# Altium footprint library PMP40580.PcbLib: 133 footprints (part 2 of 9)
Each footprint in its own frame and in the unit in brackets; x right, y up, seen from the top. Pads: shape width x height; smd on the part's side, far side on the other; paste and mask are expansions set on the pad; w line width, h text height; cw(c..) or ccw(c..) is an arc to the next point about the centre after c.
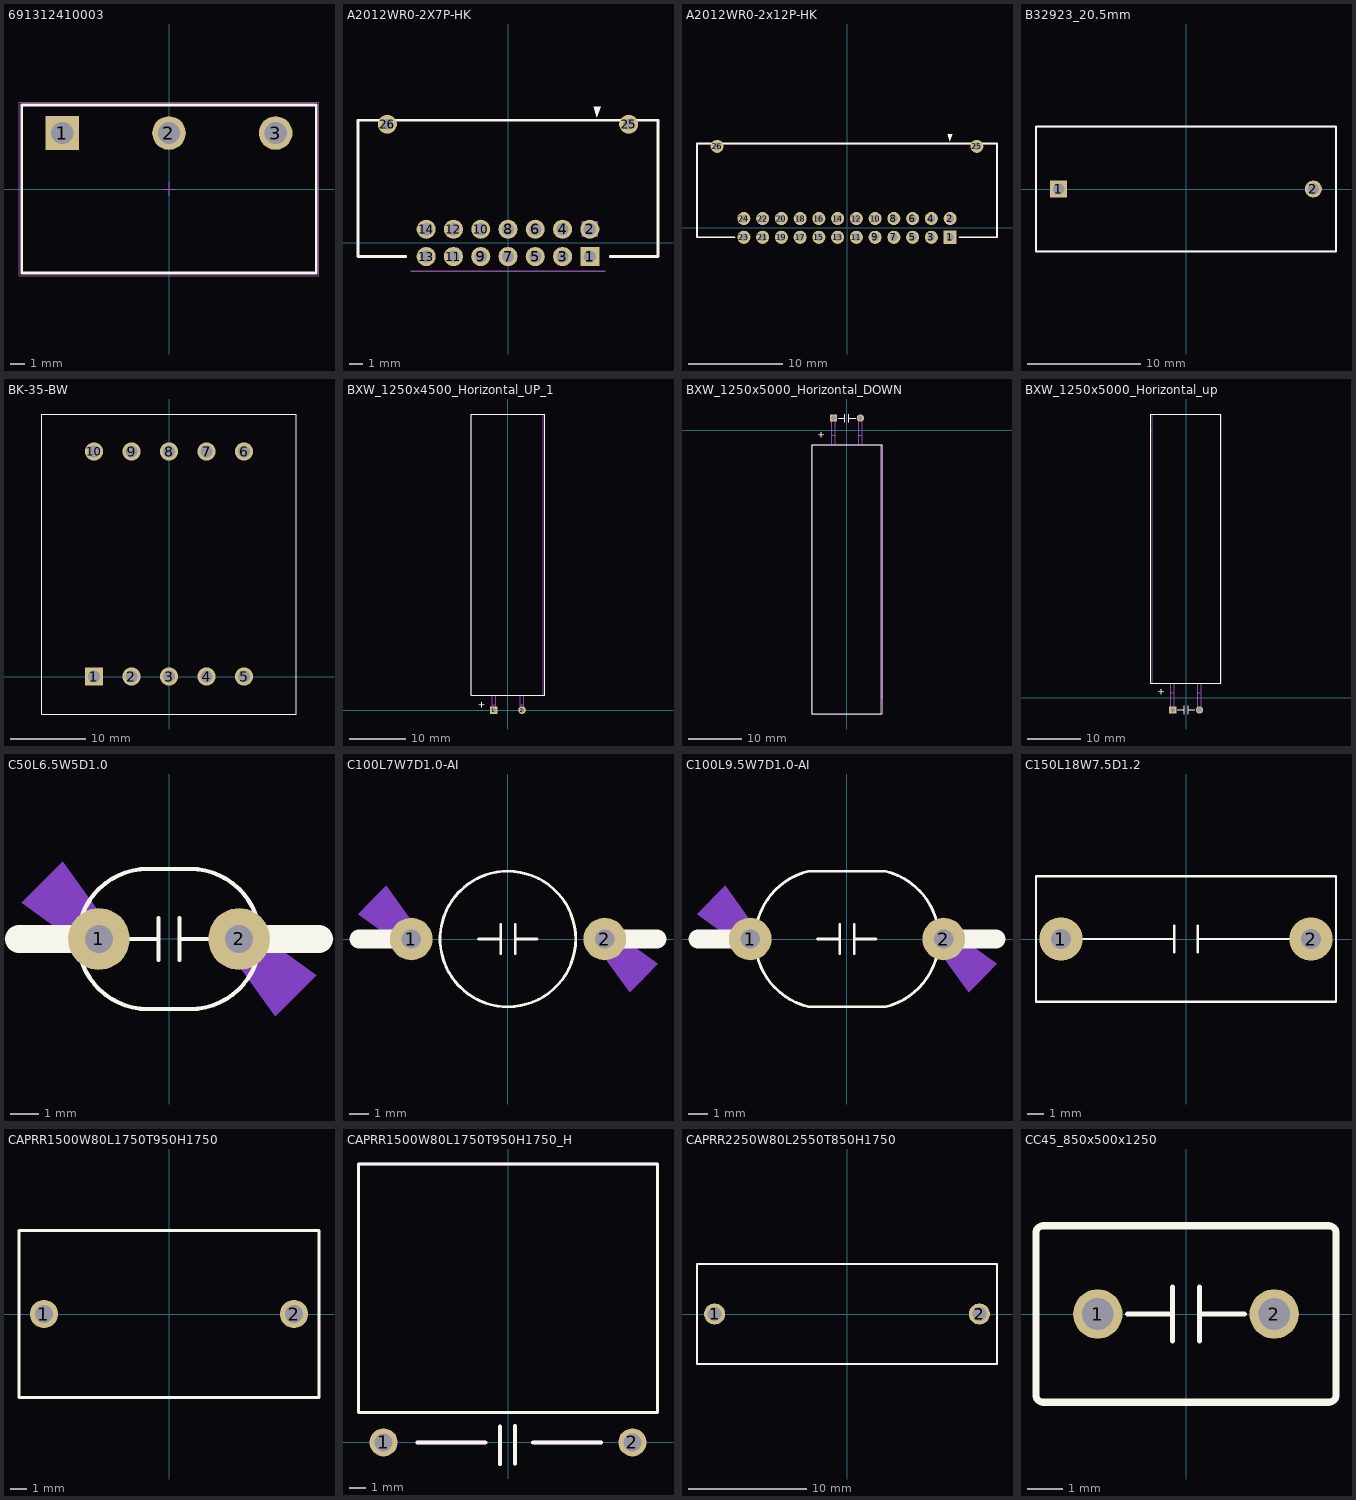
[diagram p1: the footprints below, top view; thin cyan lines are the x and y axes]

## 691312410003 [mm] "7.62 mm -Open Horizontal PCB Header - 03p"
height 8.5
pads (3):
  rect 2.4x2.4 hole 1.6: 1(-7.62,4)
  round 2.4 hole 1.6: 2(0,4) 3(7.62,4)
Top Overlay:
  lines w0.2: -10.52,-6 10.52,-6 10.52,6 -10.52,6 -10.52,-6
Mechanical 13:
  lines w0.1: -10.52,-6 -10.52,6 10.52,6 10.52,-6 -10.52,-6
Mechanical 15:
  lines w0.05: -0.5,0 0.5,0 ; 0,-0.5 0,0.5 ; -10.72,-6.2 -10.72,6.2 10.72,6.2 10.72,-6.2 -10.72,-6.2
3D body "691312410003.stp": height 8.55, standoff -3.95, extent -10.52,-6 10.52,6

## A2012WR0-2X7P-HK [mm] "Samtec"
height 4.7
pads (16):
  rect 1.4x1.4 hole 0.9 paste+0: 1(6,-1)
  round 1.4 hole 0.9 paste+0: 2(6,1) 3(4,-1) 4(4,1) 5(2,-1) 6(2,1) 7(0,-1) 8(0,1) 9(-2,-1) 10(-2,1) 11(-4,-1) 12(-4,1) 13(-6,-1) 14(-6,1)
  round 1.4 hole 0.8 mask+0: 25(8.85,8.7) 26(-8.85,8.7)
Top Overlay:
  region: 6.525,9.225 6.8,10 6.3,10
  lines w0.2: -7.5,-1 -11,-1 -11,9 11,9 11,-1 7.5,-1
Mechanical 5:
  region: 6.609,1.6 5.406,1.6 5.406,0.422 6.609,0.422
  lines w0.1: -7.125,-2.095 7.125,-2.095
  text ".Designator" at -1.827,-0.516 h1.02

## A2012WR0-2x12P-HK [mm] "A2012WR0-2x12P-HK"
height 5.8
pads (26):
  rect 1.4x1.4 hole 0.8 mask+0: 1(11,-1)
  round 1.4 hole 0.8 mask+0: 2(11,1) 3(9,-1) 4(9,1) 5(7,-1) 6(7,1) 7(5,-1) 8(5,1) 9(3,-1) 10(3,1) 11(1,-1) 12(1,1) 13(-1,-1) 14(-1,1) 15(-3,-1) 16(-3,1) 17(-5,-1) 18(-5,1) 19(-7,-1) 20(-7,1) 21(-9,-1) 22(-9,1) 23(-11,-1) 24(-11,1) 25(13.85,8.7) 26(-13.85,8.7)
Top Overlay:
  region: 10.975,9.225 11.25,10 10.75,10
  lines w0.2: -12,-1 -16,-1 -16,9 16,9 16,-1 12,-1
Mechanical 5:
  lines w0.1: -12,-1 -16,-1 -16,9 16,9 16,-1 12,-1
  text ".Designator" at 2.075,0.5 h1.02

## B32923_20.5mm [mm] "Epcos film capacitors, 22.5mm spacing"
height 20.5
pads (2):
  rect 1.5x1.5 hole 1: 1(-11.25,0)
  round 1.5 hole 1: 2(11.25,0)
Top Overlay:
  lines w0.178: -13.25,-5.5 0,-5.5 13.25,-5.5 13.25,0 13.25,5.5 0,5.5 -13.25,5.5 -13.25,0 -13.25,-5.5
Mechanical 5:
  lines w0.127: -13.25,-5.5 -13.25,0 -13.25,5.5 0,5.5 13.25,5.5 13.25,0 13.25,-5.5 0,-5.5 -13.25,-5.5
  text ".Designator" at -1.524,-0.508 h1.02
3D body: height 20.5, standoff 0, extent -13.249,-5.499 13.249,5.499

## BK-35-BW [mm]
height 10
pads (10):
  rrect4% 2.45x2.45 hole 1.6 paste-1000 mask+0: 1(-10,0)
  round 2.45 hole 1.6 paste-1000 mask+0: 2(-5,0) 3(0,0) 4(5,0) 5(10,0) 6(10,30) 7(5,30) 8(0,30) 9(-5,30) 10(-10,30)
Top Overlay:
  lines w0.127: -17,-5 -17,35 17,35 17,-5 -17,-5

## BXW_1250x4500_Horizontal_UP_1 [mm] "TH, 2-Leads, Dia 12.5mm, Pin Spacing 5mm"
height 13
pads (2):
  rect 1.35x1.35 hole 0.85: 1(-2.5,0)
  round 1.35 hole 0.85: 2(2.5,0)
Top Overlay:
  lines w0.2: -6.498,2.694 6.299,2.694 6.501,2.694 6.501,49.694 6.501,52.7 -6.498,52.7 -6.498,2.694
  text "+" at -4.15,0.3 h1.2
Mechanical 5:
  lines w0.1: -2.798,2.694 -2.798,0.944 ; -2.198,2.694 -2.198,0.944 ; 2.202,2.694 2.202,0.944 ; 2.802,2.694 2.802,0.944 ; 6.3,52.7 6.299,2.694 ; -2.798,0.944 -2.198,0.944 ; -2.798,0.944 -2.798,0.044 ccw(c-2.498,0.044) -2.198,0.044 -2.198,0.944 ; 2.202,0.944 2.802,0.944 ; 2.202,0.944 2.202,0.044 ccw(c2.502,0.044) 2.802,0.044 2.802,0.944 ; 6.299,2.694 -6.498,2.694 -6.498,52.7 6.501,52.7 6.501,49.694 6.501,2.694 6.299,2.694
  text "+" at -4.15,0.3 h1.2
  text ".Designator" at -2.4,3.7 h1.85
3D body "BXW_1250x4500_Horizontal_UP.stp": height 13, standoff -4, extent -6.498,-0.255 6.481,49.694

## BXW_1250x5000_Horizontal_DOWN [mm] "TH, 2-Leads, Dia 12.5mm, Pin Spacing 5mm"
height 13
pads (2):
  rect 1.35x1.35 hole 0.85: 1(-2.5,2.3)
  round 1.35 hole 0.85: 2(2.5,2.3)
Top Overlay:
  lines w0.15: -1.651,2.286 -0.381,2.286 ; -0.381,1.524 -0.381,3.048 ; 0.381,1.524 0.381,3.048 ; 0.381,2.286 1.651,2.286
  lines w0.2: -6.481,-52.694 6.518,-52.694 6.518,-2.694 -6.481,-2.694 -6.481,-52.694
  text "+" at -5.3,-0.2 h1.2
Bottom Overlay:
  lines w0.15: -1.651,2.286 -0.381,2.286 ; -1.651,2.286 -0.381,2.286 ; -1.651,2.286 -0.381,2.286 ; -0.381,1.524 -0.381,3.048 ; -0.381,1.524 -0.381,3.048 ; -0.381,1.524 -0.381,3.048 ; 0.381,1.524 0.381,3.048 ; 0.381,1.524 0.381,3.048 ; 0.381,1.524 0.381,3.048 ; 0.381,2.286 1.651,2.286 ; 0.381,2.286 1.651,2.286 ; 0.381,2.286 1.651,2.286
Mechanical 5:
  lines w0.1: -2.791,-2.694 -2.791,-0.944 ; -2.191,-2.694 -2.191,-0.944 ; 2.2,2.3 cw(c2.5,2.3) 2.8,2.3 ; 2.209,-2.694 2.209,-0.944 ; 2.209,2.3 2.209,-0.944 ; 2.809,-2.694 2.809,-0.944 ; 2.809,2.3 2.809,-0.944 ; 6.306,-49.694 6.306,-2.694 ; -2.791,-0.944 -2.791,2.3 cw(c-2.491,2.3) -2.191,2.3 -2.191,-0.944 ; -2.791,-0.944 -2.191,-0.944 ; 2.209,-0.944 2.809,-0.944 ; 6.306,-2.694 -6.491,-2.694 -6.491,-52.7 6.316,-52.7 6.316,-49.694 ; 6.306,-2.694 6.316,-2.694 ; 6.316,-49.694 6.519,-49.694 6.519,-2.694 6.316,-2.694 ; 6.316,-49.694 6.316,-2.694
  text ".Designator" at -2.8,-5.5 h1.85
  text "+" at -5.3,-0.2 h1.2
3D body "BXW_1250x4500_Horizontal_UP.stp": height 13, standoff -4, extent -6.49,-47.409 6.489,2.54

## BXW_1250x5000_Horizontal_up [mm] "TH, 2-Leads, Dia 12.5mm, Pin Spacing 5mm"
height 13
pads (2):
  rect 1.35x1.35 hole 0.85: 1(-2.5,-2.3)
  round 1.35 hole 0.85: 2(2.5,-2.3)
Top Overlay:
  lines w0.15: -1.651,-2.286 -0.381,-2.286 -1.651,-2.286 ; -0.381,-3.048 -0.381,-1.524 -0.381,-3.048 ; 0.381,-3.048 0.381,-1.524 0.381,-3.048 ; 0.381,-2.286 1.651,-2.286 0.381,-2.286
  lines w0.2: -6.518,2.694 -6.518,52.694 6.481,52.694 6.481,2.694 -6.518,2.694
  text "+" at -4.1,0.3 h1.2
Bottom Overlay:
  lines w0.15: -1.651,-2.286 -0.381,-2.286 -1.651,-2.286 ; -0.381,-3.048 -0.381,-1.524 -0.381,-3.048 ; 0.381,-3.048 0.381,-1.524 0.381,-3.048 ; 0.381,-2.286 1.651,-2.286 0.381,-2.286
Mechanical 5:
  lines w0.1: -6.306,49.694 -6.306,2.694 ; -2.809,-2.3 -2.809,0.944 ; -2.809,2.694 -2.809,0.944 ; -2.8,-2.3 ccw(c-2.5,-2.3) -2.2,-2.3 ; -2.209,-2.3 -2.209,0.944 ; -2.209,2.694 -2.209,0.944 ; 2.191,2.694 2.191,0.944 ; 2.791,2.694 2.791,0.944 ; -6.316,2.694 -6.316,49.694 ; -6.316,2.694 -6.306,2.694 ; -6.316,2.694 -6.519,2.694 -6.519,49.694 -6.316,49.694 ; -6.316,49.694 -6.316,52.7 6.491,52.7 6.491,2.694 -6.306,2.694 ; -2.809,0.944 -2.209,0.944 ; 2.191,0.944 2.791,0.944 ; 2.191,0.944 2.191,-2.3 ccw(c2.491,-2.3) 2.791,-2.3 2.791,0.944
  text "+" at -4.1,0.3 h1.2
  text ".Designator" at 2.8,5.5 h1.85

## C50L6.5W5D1.0 [mm]
pads (2):
  round 2.2 hole 1: 1(-2.5,0) 2(2.5,0)
Top Layer keep-out:
  region: 3.989,-2.55 4.922,-1.617 2.87,0.437 2.744,0.521 2.523,0.566 2.301,0.521 2.113,0.396 1.988,0.208 1.944,-0.014 1.988,-0.235 2.112,-0.422 2.119,-0.414
  region: -3.988,2.55 -4.922,1.616 -2.869,-0.438 -2.744,-0.522 -2.522,-0.566 -2.3,-0.522 -2.112,-0.396 -1.987,-0.208 -1.943,0.013 -1.987,0.235 -2.111,0.421 -2.119,0.413
Bottom Layer:
  region: 4.05,-0.72 4.05,-0.621 3.974,-0.437 3.833,-0.296 3.649,-0.22 3.55,-0.22 3.451,-0.22 3.267,-0.296 3.126,-0.437 3.05,-0.621 3.05,-0.72 3.05,-0.819 3.126,-1.003 3.267,-1.144 3.451,-1.22 3.55,-1.22 3.649,-1.22 3.833,-1.144 3.974,-1.003 4.05,-0.819
  region: -3.09,0.77 -3.09,0.869 -3.166,1.053 -3.307,1.194 -3.491,1.27 -3.59,1.27 -3.689,1.27 -3.873,1.194 -4.014,1.053 -4.09,0.869 -4.09,0.77 -4.09,0.671 -4.014,0.487 -3.873,0.346 -3.689,0.27 -3.59,0.27 -3.491,0.27 -3.307,0.346 -3.166,0.487 -3.09,0.671
  region: 3.96,-0.457 3.264,0.641 3.018,0.813 1.928,-0.743 2.174,-0.915 3.444,-1.194
  region: -4,0.507 -3.304,-0.591 -3.058,-0.763 -1.968,0.793 -2.214,0.965 -3.484,1.244
Bottom Layer keep-out:
  region: 3.788,-2.75 5.253,-1.285 2.869,0.436 2.119,-0.414
  region: -3.788,2.75 -5.253,1.285 -2.869,-0.437 -2.119,0.413
Top Overlay:
  lines w0.15: -1.525,0 -0.375,0 -1,0 ; 1,0 0.375,0 1.506,0 ; -0.75,-2.5 cw(c-0.75,0) -0.75,2.5 0.75,2.5 cw(c0.75,0) 0.75,-2.5 -0.75,-2.5 ; -0.375,-0.75 -0.375,0.75 -0.375,-0.75 ; 0.375,-0.75 0.375,0.75 0.375,-0.75
  lines w1: -5.35,0 -2.5,0 ; 2.5,0 5.35,0

## C100L7W7D1.0-AI [mm]
pads (2):
  round 2.2 hole 1: 1(-5,0) 2(5,0)
Top Layer keep-out:
  region: -6.488,2.55 -7.422,1.616 -5.369,-0.438 -5.244,-0.522 -5.022,-0.566 -4.8,-0.522 -4.612,-0.396 -4.487,-0.208 -4.443,0.013 -4.487,0.235 -4.611,0.421 -4.619,0.413
  region: 6.489,-2.55 7.422,-1.617 5.37,0.437 5.244,0.521 5.023,0.566 4.801,0.521 4.613,0.396 4.488,0.208 4.444,-0.014 4.488,-0.235 4.612,-0.422 4.619,-0.414
Bottom Layer:
  region: -6.5,0.507 -5.804,-0.591 -5.558,-0.763 -4.468,0.793 -4.714,0.965 -5.984,1.244
  region: 6.46,-0.457 5.764,0.641 5.518,0.813 4.428,-0.743 4.674,-0.915 5.944,-1.194
  region: -5.59,0.77 -5.59,0.869 -5.666,1.053 -5.807,1.194 -5.991,1.27 -6.09,1.27 -6.189,1.27 -6.373,1.194 -6.514,1.053 -6.59,0.869 -6.59,0.77 -6.59,0.671 -6.514,0.487 -6.373,0.346 -6.189,0.27 -6.09,0.27 -5.991,0.27 -5.807,0.346 -5.666,0.487 -5.59,0.671
  region: 6.55,-0.72 6.55,-0.621 6.474,-0.437 6.333,-0.296 6.149,-0.22 6.05,-0.22 5.951,-0.22 5.767,-0.296 5.626,-0.437 5.55,-0.621 5.55,-0.72 5.55,-0.819 5.626,-1.003 5.767,-1.144 5.951,-1.22 6.05,-1.22 6.149,-1.22 6.333,-1.144 6.474,-1.003 6.55,-0.819
Bottom Layer keep-out:
  region: -6.288,2.75 -7.753,1.285 -5.369,-0.437 -4.619,0.413
  region: 6.288,-2.75 7.753,-1.285 5.369,0.436 4.619,-0.414
Top Overlay:
  lines w0.15: -1.525,0 -0.375,0 -1,0 ; -0.251,-3.5 cw(c0,0) -0.251,3.5 ; -0.25,-3.5 0,-3.5 ccw(c0,0) 0,3.5 -0.25,3.5 ; 1,0 0.375,0 1.506,0 ; -0.375,-0.75 -0.375,0.75 -0.375,-0.75 ; 0.375,-0.75 0.375,0.75 0.375,-0.75
  lines w1: -7.7,0 -5,0 ; 5,0 7.7,0

## C100L9.5W7D1.0-AI [mm]
pads (2):
  round 2.2 hole 1: 1(-5,0) 2(5,0)
Top Layer keep-out:
  region: 6.489,-2.55 7.422,-1.617 5.37,0.437 5.244,0.521 5.023,0.566 4.801,0.521 4.613,0.396 4.488,0.208 4.444,-0.014 4.488,-0.235 4.612,-0.422 4.619,-0.414
  region: -6.488,2.55 -7.422,1.616 -5.369,-0.438 -5.244,-0.522 -5.022,-0.566 -4.8,-0.522 -4.612,-0.396 -4.487,-0.208 -4.443,0.013 -4.487,0.235 -4.611,0.421 -4.619,0.413
Bottom Layer:
  region: 6.55,-0.72 6.55,-0.621 6.474,-0.437 6.333,-0.296 6.149,-0.22 6.05,-0.22 5.951,-0.22 5.767,-0.296 5.626,-0.437 5.55,-0.621 5.55,-0.72 5.55,-0.819 5.626,-1.003 5.767,-1.144 5.951,-1.22 6.05,-1.22 6.149,-1.22 6.333,-1.144 6.474,-1.003 6.55,-0.819
  region: -5.59,0.77 -5.59,0.869 -5.666,1.053 -5.807,1.194 -5.991,1.27 -6.09,1.27 -6.189,1.27 -6.373,1.194 -6.514,1.053 -6.59,0.869 -6.59,0.77 -6.59,0.671 -6.514,0.487 -6.373,0.346 -6.189,0.27 -6.09,0.27 -5.991,0.27 -5.807,0.346 -5.666,0.487 -5.59,0.671
  region: 6.46,-0.457 5.764,0.641 5.518,0.813 4.428,-0.743 4.674,-0.915 5.944,-1.194
  region: -6.5,0.507 -5.804,-0.591 -5.558,-0.763 -4.468,0.793 -4.714,0.965 -5.984,1.244
Bottom Layer keep-out:
  region: 6.288,-2.75 7.753,-1.285 5.369,0.436 4.619,-0.414
  region: -6.288,2.75 -7.753,1.285 -5.369,-0.437 -4.619,0.413
Top Overlay:
  lines w0.15: -2.002,3.5 ccw(c-1.149,0) -1.996,-3.501 ; -2,-3.5 2,-3.5 ; -2,3.5 2,3.5 ; -1.525,0 -0.375,0 -1,0 ; 1,0 0.375,0 1.506,0 ; 1.996,3.501 cw(c1.15,0) 2.003,-3.499 ; -0.375,-0.75 -0.375,0.75 -0.375,-0.75 ; 0.375,-0.75 0.375,0.75 0.375,-0.75
  lines w1: -7.7,0 -5,0 ; 5,0 7.7,0

## C150L18W7.5D1.2 [mm]
pads (2):
  round 2.6 hole 1.2: 1(-7.5,0) 2(7.5,0)
Top Overlay:
  lines w0.15: -7.5,0 -0.75,0 ; -0.7,-0.8 -0.7,0.8 ; 0.7,-0.8 0.7,0.8 ; 0.75,0 7.5,0 ; -9,-3.75 -9,3.75 9,3.75 9,-3.75 -9,-3.75

## CAPRR1500W80L1750T950H1750 [mm] "PANASONIC"
height 18
pads (2):
  round 1.7 hole 1.069: 1(-7.5,0) 2(7.5,0)
Top Overlay:
  lines w0.17: -9,-5 -9,5 9,5 9,-5 -9,-5
Mechanical 5:
  lines w0.1: -9,-5 -9,5 9,5 9,-5 -9,-5
  text ".Designator" at -2.032,-0.508 h1.02
3D body: height 18, standoff 0, extent -8.999,-4.999 8.999,4.999
3D body: height 6, standoff -2, extent -7.797,-0.299 -7.2,0.3
3D body: height 6, standoff -2, extent 7.203,-0.299 7.8,0.3

## CAPRR1500W80L1750T950H1750_H [mm] "PANASONIC"
height 18
pads (2):
  round 1.7 hole 1.069: 1(-7.5,0) 2(7.5,0)
Top Overlay:
  lines w0.17: -9,1.8 -9,16.775 9,16.775 9,1.8 -9,1.8
  lines w0.254: -5.45,0 -1.375,0 ; -0.475,-1.3 -0.475,0.95 ; 0.425,-1.275 0.425,0.975 ; 1.524,0 5.599,0
Mechanical 5:
  lines w0.17: -9,1.8 9,1.8 9,16.775 -9,16.775 -9,1.8
  lines w0.254: -5.45,0 -1.375,0 ; -0.475,-1.3 -0.475,0.95 ; 0.425,-1.275 0.425,0.975 ; 1.524,0 5.599,0
  text ".Designator" at -3.048,-2.794 h1.02
3D body: height 6, standoff -2, extent 7.203,-0.299 7.8,0.3
3D body: height 6, standoff -2, extent -7.797,-0.299 -7.2,0.3

## CAPRR2250W80L2550T850H1750 [mm] "PANASONIC"
height 17.5
pads (2):
  round 1.8 hole 1.2: 1(-11.25,0) 2(11.25,0)
Top Overlay:
  lines w0.2: -12.75,-4.25 -12.75,4.25 12.75,4.25 12.75,-4.25 -12.75,-4.25
Mechanical 5:
  lines w0.1: -12.75,-4.25 12.75,-4.25 12.75,4.25 -12.75,4.25 -12.75,-4.25
  text ".Designator" at -2.3,-0.5 h1.02
3D body: height 6, standoff -2, extent -11.548,-0.299 -10.95,0.3
3D body: height 6, standoff -2, extent 10.952,-0.299 11.55,0.3
3D body: height 17.5, standoff 0, extent -12.75,-4.25 12.75,4.25

## CC45_850x500x1250 [mm] "TH, 2-Leads, Dia 8.5mm, Pin Spacing 5mm"
height 12.5
pads (2):
  round 1.4 hole 0.9: 1(-2.5,0) 2(2.5,0)
Top Overlay:
  lines w0.15: -1.651,0 -0.381,0 ; -0.381,-0.762 -0.381,0.762 ; 0.381,-0.762 0.381,0.762 ; 0.381,0 1.651,0
  lines w0.2: -4.25,-2.3 ccw(c-4.05,-2.3) -4.05,-2.5 4.05,-2.5 ccw(c4.05,-2.3) 4.25,-2.3 4.25,2.3 ccw(c4.05,2.3) 4.05,2.5 -4.05,2.5 ccw(c-4.05,2.3) -4.25,2.3 -4.25,-2.3
Bottom Overlay:
  lines w0.15: -1.651,0 -0.381,0 ; -0.381,-0.762 -0.381,0.762 ; 0.381,-0.762 0.381,0.762 ; 0.381,0 1.651,0
Mechanical 5:
  lines w0.1: -4.25,-2.3 ccw(c-4.05,-2.3) -4.05,-2.5 4.05,-2.5 ccw(c4.05,-2.3) 4.25,-2.3 4.25,2.3 ccw(c4.05,2.3) 4.05,2.5 -4.05,2.5 ccw(c-4.05,2.3) -4.25,2.3 -4.25,-2.3
  text ".Designator" at -1.624,-0.508 h1.02
3D body "CC45_850x500x1250.stp": height 12.5, standoff -4.37, extent -4.25,-2.5 4.25,2.5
